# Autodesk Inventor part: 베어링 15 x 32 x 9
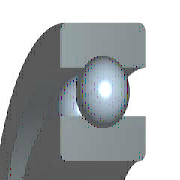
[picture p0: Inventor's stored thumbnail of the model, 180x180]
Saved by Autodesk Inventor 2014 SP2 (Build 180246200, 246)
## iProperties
IsCustomPart: 0
Created: 2012-02
Part Number: 베어링 15 x 32 x 9
Material: 강철, 연강
Description: 깊은 그루브 볼 베어링
Document SubType Name: Modeling
Standard: KS B 2023
Designer: mduedu
Standards Organization: KS
Language: ko-KR
Size Designation: 6002 - 15 x 32 x 9
Categories: <MemberInstance><Categories><Category DisplayName="샤프트 부품" InternalName="7f7aeb1f-a693-4053-b835-cee3144e0d98" Mnemonic="SHFT"><Category DisplayName="베어링" Inter
Density: 1 g/cm^3
Appearance: 강철
Author: mduedu
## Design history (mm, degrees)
sketch "스케치" dims "d0" = 4.42 (= -0.26 x WD + 0.26 x BD)
  geometry: L1 (2.29, 11.75)-(6.71, 11.75); L2 (4.5, 11.75)-(4.5, 9.54); L3 (4.5, 11.75)-(4.5, 13.96); L4 (2.858, 10.271)-(0, 10.271); L5 (0, 7.5)-(9, 7.5); L6 (2.858, 13.229)-(0, 13.229); L7 (0, 16)-(9, 16); L8 (9, 7.5)-(9, 10.271); L9 (6.142, 10.271)-(9, 10.271); L10 (6.142, 13.229)-(9, 13.229); L11 (9, 16)-(9, 13.229); L12 (-1.4, 0)-(8.4, 0) reference; L13 (0, -0.3)-(0, 5.3) reference
  constraints: 22 end point, 4 point on line, 2 collinear, 2 perpendicular, 2 symmetric about line, 1 midpoint, 1 parallel, 14 other
  dimensions: "d9" = 15 diameter of L5 L12 (= WD); "d11" = 32 diameter of L7 L12 (= BD); "d12" = 9 distance between parallel lines of L8 L13 (= KB); "d13" = 20.542 diameter of L9 L12 (= 0.326 x BD + 0.674 x WD)
revolve "본체" stored, may be unused: angle "d6" = 90 deg
revolve "볼" stored, may be unused: angle "d7" = 90 deg
pattern_circular "IDS_ARRAYBALL[SIMPL:T]" dims angle "d3" = 360 deg
body "Solid1"
fillet "모깎기1" dims "d1" = 0.3 (= KRS)
other parameters: "WD" = 15 [user parameter; used in 5 equation terms], "BD" = 32 [user parameter; used in 5 equation terms], "KB" = 9 [user parameter; used in 1 equation term], "KRS" = 0.3 [user parameter; used in 1 equation term], "d4" = 0, "d5" = 0, "d8" = 0, "d14" = 0, "d15" = 0, "BBA" = 0 [user parameter], "BC0" = 2850000 [user parameter], "BC" = 5590000 [user parameter], "BR" = 16 (= 0.5 x BD) [user parameter], "WR" = 7.5 (= 0.5 x WD) [user parameter]
